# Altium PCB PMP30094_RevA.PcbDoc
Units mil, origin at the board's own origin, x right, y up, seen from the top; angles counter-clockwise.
Board outline 6725 x 2037.5 mil, 2 copper layers (Top Layer, Bottom Layer), stack 62 mil thick; 109 components, 57 nets, 240 pads, 21 vias.
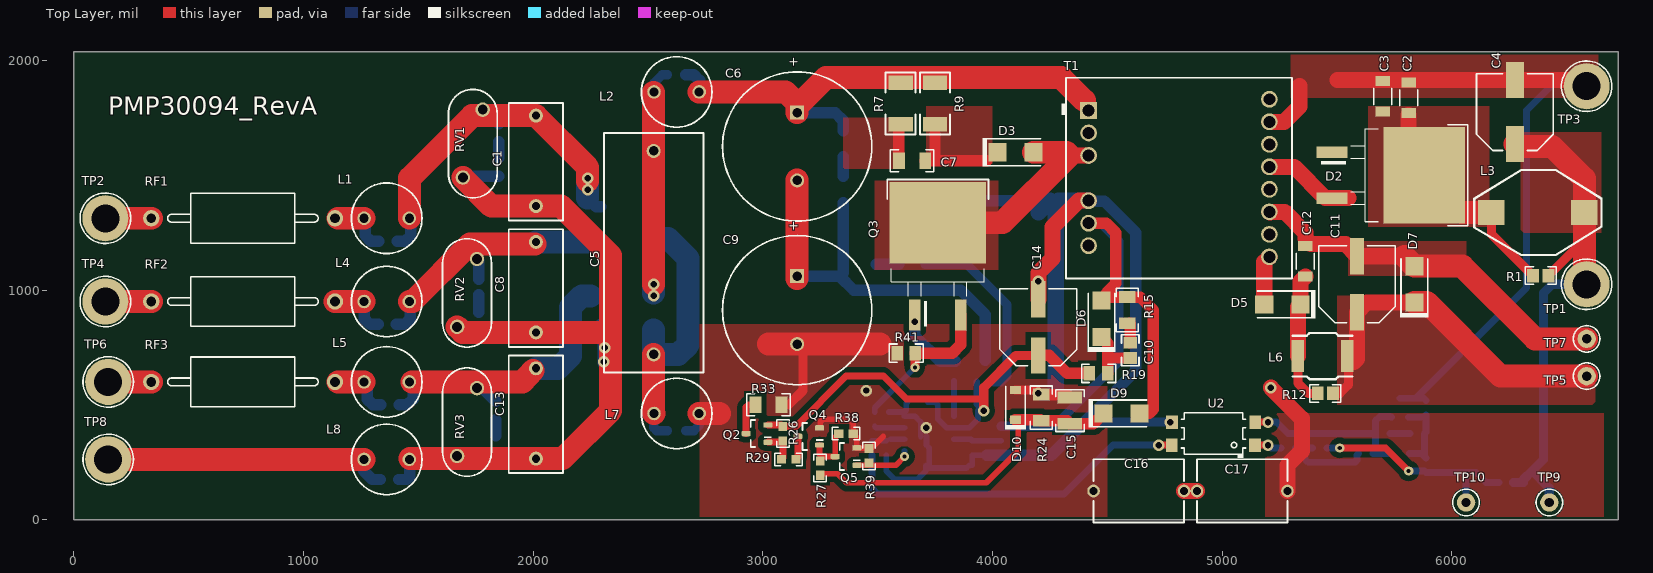
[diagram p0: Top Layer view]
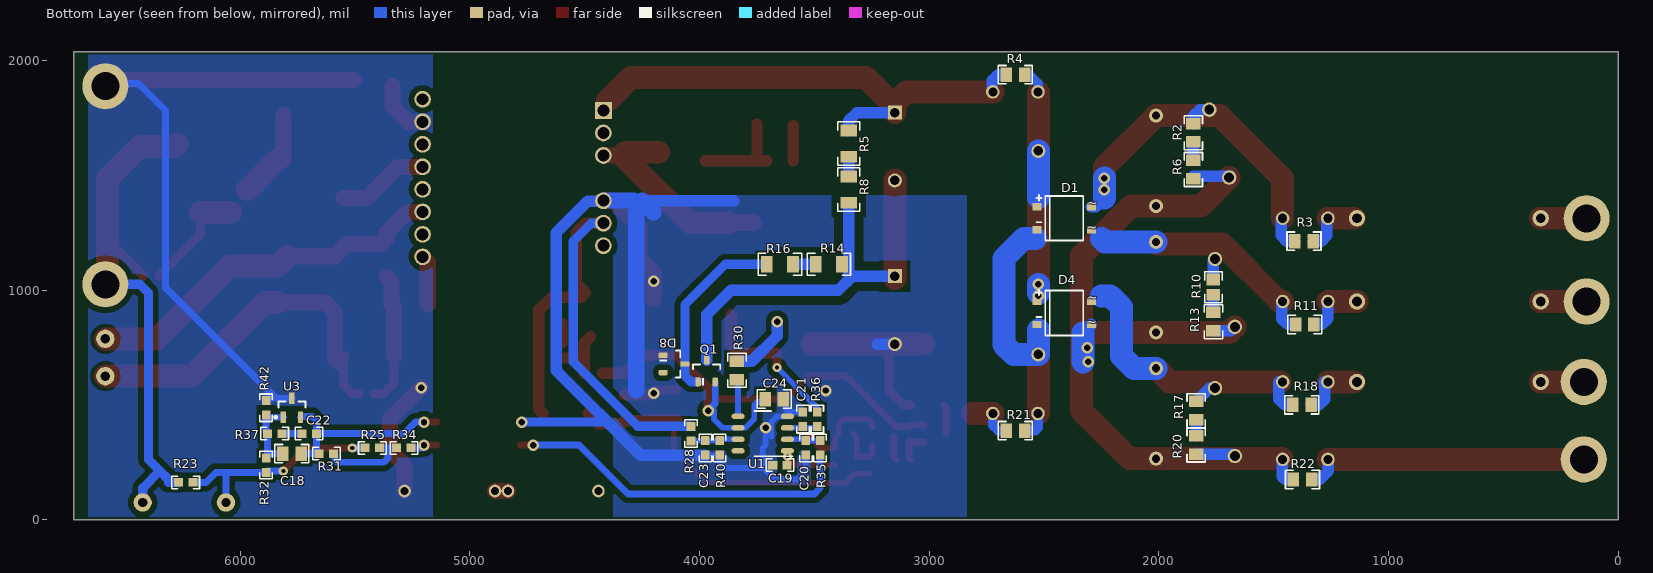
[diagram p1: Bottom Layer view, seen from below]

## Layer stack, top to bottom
Top Solder: solder mask 0.4, Solder Resist, Dk 3.5
Top Layer: signal copper 1.4
Dielectric1: core 59.2, FR-4, Dk 4.8
Bottom Layer: signal copper 1.4
Bottom Solder: solder mask 0.4, Solder Resist, Dk 3.5

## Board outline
0,0 6725,0 6725,2037.5 0,2037.5

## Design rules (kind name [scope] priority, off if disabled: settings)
AcuteAngle [All] p1: minimum=4.50000000000000E+0001 checktracksonly=FALSE
AssemblyTestPointUsage [All] p1: valid=2
Clearance Clearance_2 [InNet('PGND') vs InNet('NetR14_1')] p1: gap=40
Clearance Clearance_1 [InNet('PGND') vs InNet('NetC6_2')] p2: gap=40
Clearance Clearance_Keepouts [((IsTrack Or IsArc) And Not InPoly) And IsFree and IsKeepOut vs ((IsTrack Or IsArc) And Not InPoly) And IsFree and IsKeepOut] p3: gap=0
Clearance Clearance_BoardEdge_MountingHoles [OnCopper and InComponentClass('Mounting Holes') vs IsKeepOut] p4: gap=40
Clearance Clearance_BoardEdge_Poly [OnCopper and InPoly vs IsKeepOut] p5: gap=25
Clearance Clearance_BoardEdge [OnCopper and Not InComponentClass('Logo') and not InComponentClass('FiducialMark') and not InRegion(1000,500,4000,800) and Not IsKeepout vs IsKeepOut] p6: gap=25
Clearance Clearance_Poly [InPolygon] p7: gap=25
Clearance [All] p8: gap=7.87
ComponentClearance ComponentClearance_MountingHoles_FiducialMarks [InComponentClass('Mounting Holes') vs InComponentClass('FiducialMark')] p1: gap=50 collisioncheckmode=3 verticalgap=10 showdistances=FALSE
ComponentClearance ComponentClearance_Shunt [InComponentClass('Header') vs InComponentClass('Shunt')] p2: gap=0 collisioncheckmode=3 verticalgap=0 showdistances=FALSE
ComponentClearance ComponentClearance_Logo [InComponentClass('Logo')] p3: gap=50 collisioncheckmode=3 verticalgap=10 showdistances=FALSE
ComponentClearance ComponentClearance_ScrewToNut [(HasFootprint('NY PMS 440 0025 PH')) vs (HasFootprint('Keystone_1902C'))] p4: gap=5 collisioncheckmode=3 verticalgap=10 showdistances=FALSE
ComponentClearance ComponentClearance_MountingHoles [InComponentClass('Mounting Holes')] p5: gap=20 collisioncheckmode=3 verticalgap=100000 showdistances=FALSE
ComponentClearance ComponentClearance_SmallPassives [HasFootprint('0201*') or HasFootprint('0402*') or HasFootprint('0508') or HasFootprint('0603*') or HasFootprint('0612') or HasFootprint('0805*') or HasFootprint('0815*') or HasFootprint('0830*') or HasFootprint('1206*') or HasFootprint('1210*') or HasFootprint('1808*') or HasFootprint('1812*') or HasFootprint('1825*') or HasFootprint('2010*') or HasFootprint('2220*') or HasFootprint('2225*') or HasFootprint('2512*') or HasFootprint('2728*') or HasFootprint('3518*') vs HasFootprint('0201*') or HasFootprint('0402*') or HasFootprint('0508') or HasFootprint('0603*') or HasFootprint('0612') or HasFootprint('0805*') or HasFootprint('0815*') or HasFootprint('0830*') or HasFootprint('1206*') or HasFootprint('1210*') or HasFootprint('1808*') or HasFootprint('1812*') or HasFootprint('1825*') or HasFootprint('2010*') or HasFootprint('2220*') or HasFootprint('2225*') or HasFootprint('2512*') or HasFootprint('2728*') or HasFootprint('3518*')] p6: gap=20 collisioncheckmode=3 verticalgap=10 showdistances=FALSE
ComponentClearance ComponentClearance_THtoSMT [IsThruComponent vs IsSMTComponent] p7: gap=20 collisioncheckmode=3 verticalgap=30 showdistances=FALSE
ComponentClearance ComponentClearance_THtoTH [IsThruComponent vs IsThruComponent] p8: gap=20 collisioncheckmode=3 verticalgap=20 showdistances=FALSE
ComponentClearance [All] p9: gap=20 collisioncheckmode=3 verticalgap=10 showdistances=FALSE
DiffPairsRouting [All] p1: maxlimit=100 minlimit=10 mostfreqgap=10 toplayer_minwidth=15 toplayer_maxwidth=15 toplayer_prefwidth=15 bottomlayer_minwidth=15 bottomlayer_maxwidth=15 bottomlayer_prefwidth=15 maxuncoupledlength=1000
FabricationTestPointUsage TestPointUsage [All] p1: valid=2 allowmultiple=FALSE
FabricationTestpoint Testpoint [All] p1: side=3 testpointundercomponent=TRUE minsize=40 maxsize=100 preferedsize=60 minholesize=0 maxholesize=40 preferedholesize=32 testpointgrid=1 allowsidetop=TRUE allowsidebottom=TRUE usegrid=TRUE gridtolerance=0.01
FanoutControl Fanout_LCC [IsLCC] p1: bgadir=Out bgaviamode=Centered fanoutstyle=Auto fanoutdirection=Alternating viagrid=1 // Fanout_LCC (Default Rule)
FanoutControl Fanout_BGA [IsBGA] p2: bgadir=Out bgaviamode=Centered fanoutstyle=Auto fanoutdirection=Alternating viagrid=1 // Fanout_BGA (Default Rule)
FanoutControl Fanout_Default [All] p4: bgadir=Out bgaviamode=Centered fanoutstyle=Auto fanoutdirection=Alternating viagrid=1 // Fanout_Default (Default Rule)
FanoutControl Fanout_Small [(CompPinCount < 5)] p5: bgadir=Out bgaviamode=Centered fanoutstyle=Auto fanoutdirection=OutThenIn viagrid=1 // Fanout_Small (Default Rule)
HoleSize [All] p1: absolutevalues=TRUE maxlimit=251 minlimit=8 maxpercent=80.000 minpercent=20.000
MinimumAnnularRing MinimumAnnularRing_ThermalPadVias [IsVia and InAnyComponent] p1: minimumring=5.91
MinimumAnnularRing [All] p2: minimumring=9
MinimumSolderMaskSliver MinimumSolderMaskSliver_Logo [InComponentClass('Logo') vs InComponentClass('Logo')] p1: minsoldermaskwidth=0.7
MinimumSolderMaskSliver [All] p2: minsoldermaskwidth=3.94
PlaneConnect [All] p1: planeconnectstyle=Relief reliefexpansion=10 reliefentries=4 reliefconductorwidth=10 reliefairgap=10
PolygonConnect [All] p1: connectstyle=Direct reliefconductorwidth=10 reliefentries=4 polygonreliefangle="90 Angle" airgapwidth=10
RoutingVias ThermalPadVias [IsVia and InAnyComponent] p1: holewidth=7.87 width=19.68 viastyle="Through Hole" minholewidth=7.87 minwidth=19.68 maxholewidth=12.99 maxwidth=23.62
RoutingVias [All] p2: holewidth=16 width=34 viastyle="Through Hole" minholewidth=7.87 minwidth=26 maxholewidth=40 maxwidth=65
SilkToBoardRegionClearance [Not ((IsComment or IsDesignator) And (Hide <> 'False')) and not InRegion(1000,500,4000,800)] p1:
SilkToSilkClearance SilkToSilkClearance_Pb-FreeLogo [(HasFootprint('Pb-Free_Overlay_Medium') OR HasFootprint('Pb-Free_Overlay_Small')) vs (HasFootprint('Pb-Free_Overlay_Medium') OR HasFootprint('Pb-Free_Overlay_Small'))] p1: silktosilkclearance=0
SilkToSilkClearance [All] p2: silktosilkclearance=0
SilkToSolderMaskClearance SilkToComonentPadClearance [IsPad and InAnycomponent] p1: minsilkscreentomaskgap=0 clearancetoexposedcopper=TRUE
SilkToSolderMaskClearance "Silk to Solder Mask Opening" [All] p2: minsilkscreentomaskgap=0 clearancetoexposedcopper=FALSE
SolderMaskExpansion [All] p1: expansion=1.97
Width [All] p1: maxlimit=100 minlimit=6 preferedwidth=10 checkconnectedcopper=TRUE
15 further rules are at their usual default settings.

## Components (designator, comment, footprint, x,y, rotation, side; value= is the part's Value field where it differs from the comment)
C1 "B32921C3104M" B32921_1300x1200x600 2012.5,1562.5 r270 top
C2 "GRM31CR71A226ME15L" 1206_180 5812.5,1837.5 r270 top
C3 "GRM31CR71A226ME15L" 1206_180 5700,1843.36 r270 top
C4 "EEE-FK1A471P" SM_RADIAL_F 6275,1775 r90 top
C5 "B32653A224J" B32653_2650x2050x1100 2525,1162.5 r270 top
C6 "EKMG401ELL330ML25S" KMG_1600x2500 3150,1625 r270 top
C7 "GRM31BR73A152KW01L" 1206 3650,1562.5 r0 top
C8 "B32921C3104M" B32921_1300x1200x600 2012.5,1012.5 r270 top
C9 "EKMG401ELL330ML25S" KMG_1600x2500 3150,912.5 r270 top
C10 "Used in BOM report" 0805 4600,737.5 r270 top
C11 "EEE-FC1A101P" SM_RADIAL_E 5587.5,1025 r90 top
C12 "C3216X7R1C106K160AC" 1206_190 5362.5,1125 r90 top
C13 "B32921C3104M" B32921_1300x1200x600 2012.5,462.5 r270 top
C14 "EEE-FC1V470P" SM_RADIAL_E 4200,837.5 r90 top
C15 "Used in BOM report" 1210 4337.5,475 r90 top
C16 "DE1E3KX332MN4AP01F" KX_1000x700 4637.5,125 r180 top
C17 "DE1E3KX332MN4AP01F" KX_1000x700 5087.5,125 r180 top
C18 "08055C153KAT2A" 0805_HV 5775,287.5 r180 bottom
C19 "GRM188R71H473KA61D" 0603 3650,237.5 r0 bottom
C20 "GRM1885C1H101JA01D" 0603 3537.5,312.5 r270 bottom
C21 "GRM1885C1H101JA01D" 0603 3550,437.5 r90 bottom
C22 "Used in BOM report" 0603 5700,375 r180 bottom
C23 "Used in BOM report" 0603 3975,312.5 r270 bottom
C24 "08055C105KAT2A" 0805_HV 3675,525 r180 bottom
D1 "MB8S-TP" MBS-1 2412.5,1312.5 r180 bottom
D2 "8TQ080S" DDPAK 5725,1500 r0 top
D3 "US1K-13-F" SMA 4100,1600 r0 top
D4 "MB8S-TP" MBS-1 2412.5,900 r180 bottom
D5 "B1100-13-F" SMA 5262.5,937.5 r180 top
D6 "ES1D-13-F" SMA 4475,875 r90 top
D7 "SMAJ10A" SMA 5837.5,1025 r90 top
D8 "BZX84C16LT1G" SOT-23 4111.42,678.05 r180 bottom
D9 "Used in BOM report" SMA 4562.5,462.5 r0 top
D10 "Used in BOM report" SOD-123 4100,500 r90 top
L1 "744772102" WE_TI_8095_Unshielded 1362.5,1312.5 r0 top
L2 "744772102" WE_TI_8095_Unshielded 2625,1862.5 r0 top
L3 "DO3308P-472MLB" DO3308P 6375,1337.5 r0 top
L4 "744772102" WE_TI_8095_Unshielded 1362.5,950 r0 top
L5 "744772102" WE_TI_8095_Unshielded 1362.5,600 r0 top
L6 "DO1608C-222MLB" DO1608C 5437.5,712.5 r0 top
L7 "744772102" WE_TI_8095_Unshielded 2625,462.5 r0 top
L8 "744772102" WE_TI_8095_Unshielded 1362.5,262.5 r0 top
Q1 "FMMT458TA" SOT-23 3969.19,647.71 r90 bottom
Q2 "MMBT3906-7-F" SOT-23 2975,375 r180 top
Q3 "STB10N95K5" DDPAK 3762.5,1137.5 r90 top
Q4 "MMBT3904-7-F" SOT-23 3200,362.5 r180 top
Q5 "MMBT3904-7-F" SOT-23 3362.5,275 r180 top
R1 "Used in BOM report" 0805 6387.5,1062.5 r0 top
R2 "Used in BOM report" 0805_HV 1850,1685 r90 bottom
R3 "CRCW080510K0FKEA" 0805_HV 1368.31,1212.5 r0 bottom
R4 "CRCW080510K0FKEA" 0805_HV 2625,1937.5 r0 bottom
R5 "CRCW1206549KFKEA" 1206 3350,1637.5 r90 bottom
R6 "Used in BOM report" 0805_HV 1850,1525 r90 bottom
R7 "CRCW201068R0JNEF" 2010 3600,1812.5 r90 top
R8 "CRCW1206549KFKEA" 1206 3350,1437.5 r90 bottom
R9 "CRCW2010100KFKEF" 2010 3750,1812.5 r90 top
R10 "Used in BOM report" 0805 1762.5,1012.5 r90 bottom
R11 "CRCW080510K0FKEA" 0805_HV 1365,850 r0 bottom
R12 "Used in BOM report" 0805 5450,550 r0 top
R13 "Used in BOM report" 0805_HV 1762.5,862.5 r90 bottom
R14 "CRCW1206499KFKEA" 1206 3437.5,1112.5 r180 bottom
R15 "Used in BOM report" 1206 4587.5,912.5 r90 top
R16 "CRCW1206499KFKEA" 1206 3650,1112.5 r180 bottom
R17 "Used in BOM report" 0805_HV 1837.5,475 r90 bottom
R18 "CRCW080510K0FKEA" 0805_HV 1377.5,500 r0 bottom
R19 "CRCW080530R1FKEA" 0805_HV 4462.5,637.5 r0 top
R20 "Used in BOM report" 0805_HV 1837.5,325 r90 bottom
R21 "CRCW080510K0FKEA" 0805_HV 2625,387.5 r0 bottom
R22 "CRCW080510K0FKEA" 0805_HV 1375,175 r0 bottom
R23 "CRCW060349R9FKEA" 0603 6237.5,162.5 r0 bottom
R24 "Used in BOM report" 1206 4212.5,487.5 r270 top
R25 "CRCW06030000Z0EA" 0603 5425,312.5 r0 bottom
R26 "Used in BOM report" 0603 3087.5,375 r90 top
R27 "Used in BOM report" 0603 3250,225 r270 top
R28 "CRCW0603324KFKEA" 0603 4037.5,375 r90 bottom
R29 "Used in BOM report" 0603 3112.5,262.5 r180 top
R30 "CRCW08050000Z0EA" 0805_HV 3837.5,650 r90 bottom
R31 "Used in BOM report" 0603 5625,287.5 r180 bottom
R32 "RCG060310K0FKEA" 0603 5887.5,237.5 r270 bottom
R33 "Used in BOM report" 1206 3025,500 r180 top
R34 "CRCW06032K05FKEA" 0603 5287.5,312.5 r0 bottom
R35 "CRCW06030000Z0EA" 0603 3475,312.5 r270 bottom
R36 "CRCW06031K13FKEA" 0603 3487.5,437.5 r90 bottom
R37 "Used in BOM report" 0603 5850,375 r0 bottom
R38 "Used in BOM report" 0603 3362.5,375 r180 top
R39 "Used in BOM report" 0603 3462.5,278.05 r270 top
R40 "RC0603FR-0724KL" 0603 3912.5,312.5 r90 bottom
R41 "ERJ-6RQF1R2V" 0805_HV 3625,725 r0 top
R42 "CRCW06033K32FKEA" 0603 5887.5,487.5 r270 bottom
RF1 "FW20A10R0JACT-ND" RES_PWR4522 737.5,1312.5 r180 top
RF2 "FW20A10R0JACT-ND" RES_PWR4522 737.5,950 r180 top
RF3 "FW20A10R0JACT-ND" RES_PWR4522 737.5,600 r180 top
RV1 "S10K275E2" VAR_S10K275E2 1737.5,1637.5 r90 top
RV2 "S10K275E2" VAR_S10K275E2 1712.5,987.5 r90 top
RV3 "S10K275E2" VAR_S10K275E2 1712.5,425 r90 top
T1 "750316395" Wurth_750316395 4812.5,1487.5 r0 top
TP1 "Suggest using a net name here" Keystone1503-2 6587.5,1025 r0 top
TP2 "Suggest using a net name here" Keystone1503-2 137.5,1312.5 r0 top
TP3 "Suggest using a net name here" Keystone1503-2 6587.5,1887.5 r0 top
TP4 "Suggest using a net name here" Keystone1503-2 137.5,950 r0 top
TP5 "5000" Keystone5000 6587.5,625 r0 top
TP6 "Suggest using a net name here" Keystone1503-2 150,600 r0 top
TP7 "5001" Keystone5001 6587.5,787.5 r0 top
TP8 "Suggest using a net name here" Keystone1503-2 150,262.5 r0 top
TP9 "5000" Keystone5000 6425,75 r0 top
TP10 "5000" Keystone5000 6062.5,75 r90 top
U1 "UCC28600D" D0008A_N 3725,375 r0 bottom
U2 "FOD817AS" N04C 4962.5,375 r180 top
U3 "LMV431AIMF/NOPB" MF03A_N 5775,487.5 r90 bottom

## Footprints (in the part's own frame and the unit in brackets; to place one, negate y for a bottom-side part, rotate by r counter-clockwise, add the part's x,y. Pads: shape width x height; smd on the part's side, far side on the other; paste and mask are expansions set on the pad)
0603 [mm] "0603 from SM-752 data"
  rect 1x0.95 smd: 1(-0.8,0) 2(0.8,0)
  silkscreen extent -1.52,-0.69 1.52,0.69, body extent -0.87,-0.47 0.87,0.47, height 1
0805 [mm] "0805 from SM-752 data"
  rect 1.3x1.5 smd: 1(-0.85,0) 2(0.85,0)
  silkscreen extent -1.72,-0.97 1.72,0.97, body extent -1.1,-0.72 1.1,0.72, height 1.45
0805_HV [mil] "0805 with 30mil clearance between pads"
  rect 50x63 smd: 1(-40,0) 2(40,0)
  silkscreen extent -74,-40 74,40, body extent -43,-29 43,29, height 57
1206 [mm] "1206 from SM-752 data"
  rect 1.3x1.85 smd: 1(-1.45,0) 2(1.45,0)
  silkscreen extent -2.4,-1.21 2.4,1.21, body extent -1.7,-0.9 1.7,0.9, height 1.35
1206_180 [mm] "1206_180"
  rect 1.1x1.6 smd: 1(-1.7,0) 2(1.7,0)
  silkscreen extent -0.9,-1 0.9,1, body extent -1.75,-0.95 1.75,0.95, height 1.8
1206_190 [mm] "1206_190"
  rect 1.1x1.6 smd: 1(-1.7,0) 2(1.7,0)
  silkscreen extent -0.9,-1 0.9,1, body extent -1.75,-0.95 1.75,0.95, height 1.9
1210 [mm] "1210 from SM-752 data"
  rect 1.3x2.7 smd: 1(-1.45,0) 2(1.45,0)
  silkscreen extent -2.32,-1.57 2.32,1.57, body extent -1.7,-1.35 1.7,1.35, height 1.35
2010 [mm] "Chip Capacitor, Body 5.08x2.54mm, IPC Medium Density"
  rect 1.6x2.7 smd: 1(-2.3,0) 2(2.3,0)
  silkscreen extent -3.42,-1.65 3.42,1.65, body extent -2.73,-1.45 2.73,1.45, height 1.66
B32653_2650x2050x1100 [mm] "TH, 2-Leads, Body 26.5x11mm, Pin Spacing 22.5mm"
  round 1.55 hole 1.05: 1(-11.25,0) 2(11.25,0)
  silkscreen extent -13.25,-5.5 13.25,5.5, body extent -13.25,-5.5 13.25,5.5, height 20.5
B32921_1300x1200x600 [mm] "EPCOS"
  round 1.55 hole 0.9: 1(-5,0) 2(5,0)
  silkscreen extent -6.4,-3 6.6,3, body extent -6.4,-3 6.6,3, height 12
D0008A_N [mm] "SOIC, 8-Leads, Body 4.9x3.9mm, Pitch 1.27mm, IPC Medium Density"
  oval 1.45x0.6 smd: 1(-2.725,1.905) 2(-2.725,0.635) 3(-2.725,-0.635) 4(-2.725,-1.905) 5(2.725,-1.905) 6(2.725,-0.635) 7(2.725,0.635) 8(2.725,1.905)
  silkscreen extent -3.3,-2.5 0.9,2.5, body extent -3,-2.45 3,2.45, height 1.63
DDPAK [mil] "D2-PAK, 3-Pads, Body 9.7x10.4mm (max), TO-263AB, using Vishay Silionix recommended pad sizes"
  rrect8% 135x49.49 smd: 1(-246.06,100) 3(-246.06,-100)
  rrect1% 355x420 smd paste-181.1: 4(155.51,0)
  silkscreen extent -295,-220 344,220, body extent -295,-202 324,202, height 180
DO1608C [mm] "DO1608C"
  rect 1.4x3.56 smd: 1(-2.73,0) 2(2.73,0)
  silkscreen extent -3.3,-2.55 3.3,2.55, body extent -3.27,-2.22 3.33,2.23, height 2.92
DO3308P [mil]
  rect 115x110 smd: 1(-202.5,0) 2(202.5,0)
  silkscreen extent -278,-185 278,185, body extent -255,-185 255,185, height 118
Keystone1503-2 [mm] "Double Turret"
  round 5.1 hole 3.1: 1(0,0)
  silkscreen extent -2.79,-2.79 2.79,2.79, body extent -2.4,-2.4 2.38,2.4, height 9.22
Keystone5000 [mil] "For Keystone 500x miniature loop terminals"
  round 80 hole 40: 1(0,0)
  silkscreen extent -58,-58 58,58, body extent -49,-49 49,49, height 182
Keystone5001 [mil] "For Keystone 500x miniature loop terminals"
  round 80 hole 40: 1(0,0)
  silkscreen extent -58,-58 58,58, body extent -49,-49 49,49, height 182
KMG_1600x2500 [mm] "TH, 2-Leads, 16mm Dia, Pin Spacing 7.5mm"
  rect 1.55x1.55 hole 1.05: 1(-3.75,0)
  round 1.55 hole 1.05: 2(3.75,0)
  silkscreen extent -8.25,-8.25 8.25,8.25, body extent -8.25,-8.25 8.26,8.25, height 26.51
KX_1000x700 [mm] "TH, 2-Leads, Dia 10mm, Lead Spacing 10mm"
  round 1.4 hole 0.9: 1(-5,0) 2(5,0)
  silkscreen extent -5,-3.5 5,3.5, body extent -5.32,-3.5 5.33,3.5, height 12.99
MBS-1 [mm] "SOP, 4-Leads, Body 4.95x4.2mm"
  rect 1x0.8 smd: 1(-3,1.27) 2(3,1.27) 3(3,-1.27) 4(-3,-1.27)
  silkscreen extent -3.08,-2.48 2.1,2.56, body extent -3.45,-2.47 3.45,2.48, height 2.9
MF03A_N [mm] "SOT23, 3-Leads, Body 2.9x1.3mm, Pitch 0.95mm, Lead Span 2.4mm, IPC Medium Density"
  rect 1.3x0.6 smd: 1(-1.05,0.95) 2(-1.05,-0.95) 3(1.05,0)
  silkscreen extent -1.17,-1.5 0.7,1.93, body extent -0.7,-1.5 0.7,1.5, height 1.12
N04C [mm] "FAIRCHILD"
  rect 1.3x1.5 smd mask+0.065: 1(-4.587,1.27) 2(-4.612,-1.27) 3(4.588,-1.27) 4(4.613,1.27)
  silkscreen extent -3.56,-2.3 3.56,2.72, body extent -5.08,-2.3 5.08,2.3, height 3.87
RES_PWR4522 [mm] "Bourns fusible resistor"
  round 1.8 hole 1.1: 1(-10.16,0) 2(10.16,0)
  silkscreen extent -8.3,-2.76 8.35,2.74, body extent -10.58,-2.74 10.58,2.74, height 5.49
SM_RADIAL_E [mm] "8 x 6.2mm:  Panasonic E"
  rect 4x1.6 smd: 1(-3.1,0) 2(3.1,0)
  silkscreen extent -4.25,-4.25 4.25,4.25, body extent -4.25,-4.25 4.25,4.25, height 6.5
SM_RADIAL_F [mm] "8 x 10.2mm:  Panasonic F"
  rect 4x2 smd: 1(-3.55,0) 2(3.55,0)
  silkscreen extent -4.25,-4.25 4.25,4.25, body extent -4.25,-4.25 4.25,4.25, height 10.5
SMA [mm] "Molded Diode, 2-Leads, Body 4.3x2.6mm, IPC Medium Density, based on OnSemi component dimensions and land pattern"
  rect 2x2 smd: 1(-2,0) 2(2,0)
  silkscreen extent -3.66,-1.57 2.79,1.57, body extent -2.6,-1.3 2.6,1.3, height 2.42
SOD-123 [mm] "On Semi recommended land pattern"
  rect 0.915x1.22 smd: 1(-1.637,0) 2(1.637,0)
  silkscreen extent -2.74,-1.17 2.03,1.17, body extent -1.93,-0.9 1.93,0.9, height 1.35
SOT-23 [mm] "SOT23, 3-Leads, Body 2.9x1.3mm, Pitch 0.95mm, Lead Span 2.5mm, IPC Medium Density"
  rrect50% 1x0.6 smd: 1(-1.2,0.95) 2(-1.2,-0.95) 3(1.2,0)
  silkscreen extent -1.62,-1.5 0.7,1.5, body extent -1.16,-1.45 1.21,1.45, height 1
VAR_S10K275E2 [mm] "EPCOS"
  round 1.6 hole 1.1: 1(-3.75,1.1) 2(3.75,-1.1)
  silkscreen extent -6,-2.7 6,2.7, body extent -5.98,-2.7 5.98,2.7, height 14.99
WE_TI_8095_Unshielded [mm] "TH, 2-Leads, Dia 7.8mm, Pin Spacing 5mm"
  round 1.5 hole 1: 1(-2.5,0) 2(2.5,0)
  silkscreen extent -3.9,-3.9 3.9,3.9, body extent -5.52,-5.52 5.52,5.52, height 9.5
Wurth_750316395 [mm] "TH, 14-Leads, Body 25x22.2mm, Pitch 2.49mm"
  rect 1.85x1.85 hole 1.32: 1(-10,7.48)
  round 1.85 hole 1.32: 2(-10,4.99) 3(-10,2.5) 4(-10,-2.5) 5(-10,-4.99) 6(-10,-7.48) 7(10,-8.715) 8(10,-6.225) 9(10,-3.735) 10(10,-1.245) 11(10,1.245) 12(10,3.735) 13(10,6.225) 14(10,8.715)
  silkscreen extent -13,-11.1 12.5,11.1, body extent -12.5,-11.1 12.5,11.1, height 16

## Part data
C1 C8 C13: "CAP, Film, 0.1 µF, 305 V, +/- 20%, TH"
C2 C3: "CAP, CERM, 22 µF, 10 V, +/- 20%, X7R, 1206"
C4: "CAP, AL, 470 µF, 10 V, +/- 20%, 0.16 ohm, SMD"
C5: "CAP, Film, 0.22 µF, 1000 V, +/- 5%, TH"
C6 C9: "CAP, AL, 33 µF, 400 V, +/- 20%, TH"
C7: "CAP, CERM, 1500 pF, 1000 V, +/- 10%, X7R, 1206"
C10 C15 C22 C23: library part Capacitor, "CAP, CERM, xxxF, xxV, [TempCo], xx%, [PackageReference]"
C11: "CAP, AL, 100 µF, 10 V, +/- 20%, 0.4 ohm, SMD"
C12: "CAP, CERM, 10 µF, 16 V, +/- 10%, X7R, 1206_190"
C14: "CAP, AL, 47 µF, 35 V, +/- 20%, 0.4 ohm, SMD"
C16 C17: "CAP, CERM, 3300 pF, 300 V, +/- 20%, E, D10xT7mm"
C18: "CAP, CERM, 0.015 µF, 50 V, +/- 10%, X7R, 0805"
C19: "CAP, CERM, 0.047 µF, 50 V, +/- 10%, X7R, 0603"
C20 C21: "CAP, CERM, 100 pF, 50 V, +/- 5%, C0G/NP0, 0603"
C24: "CAP, CERM, 1 µF, 50 V, +/- 10%, X7R, 0805"
D1 D4: "Diode, Switching-Bridge, 800 V, 0.5 A, 4-Pin TO269AA, Body 4.95 x 4.2 mm, Pitch 2.555 mm"
D2: library part MBRB745PBF, "Diode, Schottky, 80V, 8A, DDPAK"
D3: "Diode, Fast Rectifier, 800 V, 1 A, SMA"
D5: "Diode, Schottky, 100 V, 1 A, SMA"
D6: "Diode, Ultrafast, 200 V, 1 A, SMA"
D7: "Diode, TVS, Uni, 10 V, 400 W, SMA"
D8: "Diode, Zener, 16 V, 225 mW, SOT-23"
D9: library part Diode_Schottky, "Diode, Schottky, xxV, xxA, [PackageReference]"
D10: library part Zener, "Diode, Zener, xxV, xxxmW, [PackageReference]"
L1 L2 L4 L5 L7 L8: library part 744772221, "Inductor, Wirewound, Ferrite, 1000µH, TH"
L3: "Inductor, Drum Core, Ferrite, 4.7 µH, 3.2 A, 0.04 ohm, SMD"
L6: "Inductor, Drum Core, Ferrite, 2.2 µH, 2.3 A, 0.07 ohm, SMD"
Q1: library part "FMMT458TA, Diodes Inc.", "Transistor, NPN, 400 V, 0.225 A, SOT-23"
Q2: library part "MMBT3906-7-F, Diodes Inc.", "Transistor, PNP, 40 V, 0.2 A, SOT-23"
Q3: library part STB8N65M5, "MOSFET, N-CH, 950 V, DDPAK"
Q4 Q5: library part "MMBT3904-7-F, Diodes Inc.", "Transistor, NPN, 40 V, 0.2 A, SOT-23"
R1 R2 R6 R10 R12 R13 R15 R17 R20 R24 R26 R27 R29 R31 R33 R37 R38 R39: library part Resistor, "RES, xxx ohm, x%, xW, [PackageReference]"
R3 R4 R11 R18 R21 R22: "RES, 10.0 k, 1%, 0.125 W, 0805"
R5 R8: "RES, 549 k, 1%, 0.25 W, 1206"
R7: "RES, 68, 5%, 0.75 W, 2010"
R9: "RES, 100 k, 1%, 0.75 W, 2010"
R14 R16: "RES, 499 k, 1%, 0.25 W, 1206"
R19: "RES, 30.1, 1%, 0.125 W, 0805"
R23: "RES, 49.9, 1%, 0.1 W, 0603"
R25 R35: "RES, 0, 5%, 0.1 W, 0603"
R28: "RES, 324 k, 1%, 0.1 W, 0603"
R30: "RES, 0, 5%, 0.125 W, 0805"
R32: "RES, 10.0 k, 1%, 0.1 W, 0603"
R34: "RES, 2.05 k, 1%, 0.1 W, 0603"
R36: "RES, 1.13 k, 1%, 0.1 W, 0603"
R40: "RES, 24.0 k, 1%, 0.1 W, 0603"
R41: "RES, 1.20, 1%, 0.125 W, 0805"
R42: "RES, 3.32 k, 1%, 0.1 W, 0603"
RF1: library part PWR4522AS10R0JA, "RES, 10, 5%, 32W, Fusible, TH"
RF2 RF3: library part PWR4522AS10R0JA, "RES, 10, 5%, 2 W, Fusible, TH"
RV1 RV2 RV3: "Varistor 275V RMS 10MM Radial, TH"
T1: "Transformer, 1100 uH, TH"
TP1 TP2 TP3 TP4 TP6 TP8: library part 1503-2, "Terminal, Turret, TH, Double"
TP5 TP9 TP10: "Test Point, Miniature, Red, TH"
TP7: "Test Point, Miniature, Black, TH"
U1: "Quasi-Resonant Flyback Green-Mode Controller with Current Control, 99 % Duty Cycle, -40 to +105 degC, 8-pin SOIC (D), Green (RoHS & no Sb/Br)"
U2: "Optocoupler, 5 kV, 80-160% CTR, SMT"
U3: "Low-Voltage (1.24V) Adjustable Precision Shunt Regulators, 3-pin SOT-23, Pb-Free"

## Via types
v1: diameter 50, hole 28, Top Layer to Bottom Layer, 17 vias
v2: diameter 40, hole 18, Top Layer to Bottom Layer, 4 vias

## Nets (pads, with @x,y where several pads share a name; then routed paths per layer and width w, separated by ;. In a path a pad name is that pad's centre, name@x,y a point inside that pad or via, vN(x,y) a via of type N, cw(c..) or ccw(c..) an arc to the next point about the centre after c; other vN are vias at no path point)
GND1: C2.1 C3.1 C4.2 C17.1 R42.1 T1.13 TP3.1 U3.3 | length 3761.3
  Top Layer w70: T1.13 5270.08,1732.58 5337.5,1800 5337.5,1887.5 ; v1(5212.5,575) 5347.48,440.02 5347.48,300 5284.35,236.87 C17.1 ; 5502.26,1914.76 C4.2 6560.24,1914.76 TP3.1
  Bottom Layer w30: U3.3 5843.9,528.84 ; R42.1 5877.66,528.84 5843.9,528.84 ; TP3.1 6575,1900 6442.32,1900 6325,1782.68 6325,1009.94 5843.9,528.84
GND2: C11.2 C12.2 D7.2 T1.9 TP7.1 | length 1630.9
  Top Layer w70: T1.9@5209.15,1337.5 T1.9 5272.05,1340.45 5362.5,1250 5362.5,1225 5387.5,1200 5537.5,1200 5587.5,1150 C11.2 5794.19,1147.05
  Top Layer w100: 5794.19,1147.05 D7.2 6046.26,1103.74 6362.5,787.5 TP7.1
NetC1_1: C1.1 D1.2 L1.2 R2.2 R3.2 RV1.2 | length 1634.2
  Top Layer w100: L1.2 1462.5,1314.07 1462.5,1487.5 1734.35,1759.35 C1.1 2237.5,1534.35 v1@2237.5,1475
  Bottom Layer w50: R3.2 1443.31,1212.5 1468.31,1237.5 1468.31,1310.93 L1.2@1466.73,1312.5 ; RV1.2 1821.16,1785.14 1850,1756.3 R2.2 ; 2237.5,1400 2275,1362.5 D1.2
  Bottom Layer w100: 2237.5,1400 v1(2237.5,1487.5)
  other v1: 2237.5,1437.5
NetC1_2: C1.2 C8.2 C13.2 D4.3 L8.2 R6.1 R13.1 R20.1 R22.2 RV1.1 RV2.1 RV3.1 | length 3822.7
  Top Layer w100: L8.2@1464.07,265.65 C13.2 2128.15,265.65 2337.5,475 2337.5,1150 2121.85,1365.65 C1.2 1818.41,1365.65 RV1.1 ; RV2.1 1693.41,815.65 C8.2 2334.35,815.65
  Bottom Layer w50: R22.2 1450,175 1462.5,187.5 L8.2@1462.5,264.07 ; RV2.1 1686.55,822.5 R13.1 ; RV3.1@1676.83,285 R20.1 ; RV1.1@1689.33,1495 R6.1@1850,1495 ; D4.3 2294.39,847.93 2329.82,812.5
  Bottom Layer w100: v1@2329.82,687.5 2329.82,812.5
  other v1: 2308.46,687.5 2312.5,749.11
NetC2_2: C2.2 C3.2 D2.4 L3.1 R1.1 | length 850.9
  Top Layer w40: L3.1 6172.5,1244.04 R1.1
  Top Layer w70: D2.4@5812.5,1568.01 C2.2@5812.5,1762.5
  Top Layer w100: D2.4@5843.01,1562.5 D2.4@5968.01,1437.5 ; D2.4@6043.01,1337.5 L3.1
NetC4_1: C4.1 L3.2 R1.2 R23.2 TP1.1 TP9.1 | length 2326.6
  Top Layer w40: R1.2 6577.5,1219.04
  Top Layer w100: C4.1 6285.24,1625 6437.5,1625 6577.5,1485 L3.2 6577.5,1219.04 6577.5,1035 TP1.1
  Bottom Layer w40: R23.2 6312.5,162.5 6312.5,175 6350,212.5 ; TP9.1 6425,137.5 6350,212.5 ; TP1.1 6437.5,1025 6400,987.5 6400,262.5 6350,212.5
NetC5_1: C5.1 D1.1 D4.1 L2.1 R4.1 | length 1188.8
  Top Layer w100: v1(2525,1025) C5.1 L2.1@2525,1860.93
  Bottom Layer w40: L2.1 2525,1864.07 2525,1900 2562.5,1937.5 R4.1
  Bottom Layer w100: v1@2525,987.99 v1(2525,1025) ; 2525,1403.25 C5.1
  other v1: 2525,975
NetC5_2: C5.2 D1.4 D4.4 L7.1 R21.1 | length 1208
  Top Layer w100: C5.2 2525,464.07 L7.1
  Bottom Layer w40: L7.1 2525,460.93 2525,400 2537.5,387.5 R21.1
  Bottom Layer w100: 2525,825 C5.2 2632.09,719.59 2675,762.5 2675,1137.5 2587.5,1225 2537.5,1225
NetC6_1: C6.1 L2.2 R4.2 R5.2 R7.2 R9.2 T1.1 | length 2196.3
  Top Layer w100: L2.2 3100,1862.5 3150,1812.5 ; C6.1 3150,1800 3275,1925 4300,1925 4400,1825
  Bottom Layer w50: R4.2 2700,1937.5 2725,1912.5 2725,1864.07 L2.2 ; C6.1 3314.86,1772.64 3350,1737.5 R5.2
NetC6_2: C6.2 C9.1 Q1.3 R8.1 R14.2 | length 1842.8
  Top Layer w100: C9.1@3150,1050 C9.1 C6.2 C6.2@3150,1479.72
  Bottom Layer w50: C9.1 3335.14,1060.14 ; R8.1 3350,1075 3335.14,1060.14 ; Q1.3 3969.19,893.31 3862.5,1000 3395.28,1000 3335.14,1060.14
NetC7_1: C7.1 R7.1 | length 152.4
  Top Layer w50: C7.1 R7.1@3592.91,1714.86
NetC7_2: C7.2 D3.1 R9.1 | length 402.4
  Top Layer w50: C7.2 3975,1562.5 ; 3750,1587.5 R9.1
NetC8_1: C8.1 D1.3 L4.2 R10.2 R11.2 RV2.2 | length 1158.9
  Top Layer w50: RV2.2@1755.81,1156.69 1755.81,1181.69
  Top Layer w100: L4.2 1475,950 1725,1200 C8.1@2009.35,1200
  Bottom Layer w50: R11.2 1440,850 1465,875 1465,948.43 L4.2@1463.43,950 ; RV2.2 1762.5,1128.44 R10.2
  Bottom Layer w100: C8.1 2234.35,1209.35 2250,1225
NetC10_1: C10.1 R15.1 | length 84.4
  Top Layer w50: C10.1 R15.1@4600,855.41
NetC10_2: C10.2 D6.1 R19.2 | length 268
  Top Layer w50: D6.1 4502.5,768.76 4502.5,703.13 ; R19.2 4502.5,703.13 ; C10.2 4503.41,704.04 4502.5,703.13
NetC11_1: C11.1 D7.1 L6.2 R12.2 TP5.1 | length 1580.8
  Top Layer w40: R12.2 5512.5,550 5550,587.5 5550,707.48 L6.2
  Top Layer w70: 5575,687.5 5587.5,700 C11.1 5630.81,946.26 D7.1
  Top Layer w100: D7.1 5891.24,946.26 6212.5,625 TP5.1
NetC12_1: C12.1 D5.1 L6.1 R12.1 | length 581.7
  Top Layer w40: L6.1 5330.02,594.98 5375,550 R12.1
  Top Layer w70: L6.1 5330.02,926.28 D5.1 5341.24,1036.81 C12.1
NetC13_1: C13.1 D4.2 L5.2 R17.2 R18.2 RV3.2 | length 1292.5
  Top Layer w100: L5.2@1473.43,600 1953.15,600 C13.1@2000,650
  Bottom Layer w50: R18.2 1452.5,500 1477.5,525 1477.5,598.43 L5.2@1475.93,600 ; RV3.2 1779.86,572.64 R17.2
  Bottom Layer w100: C13.1 2109.35,659.35 2162.5,712.5 2162.5,925 2212.5,975 2250,975
NetC15_1: C15.1 D9.1 D10.1 R24.2 R27.2 | length 1474.5
  Top Layer w25: R27.2@3262.5,199.75 3262.75,200 3325,200 3364.47,160.53 3973.03,160.53 4112.5,300 4112.5,423.03 D10.1
  Top Layer w50: D10.1 4207.38,435.53 R24.2 4325,430.41 C15.1 4439.17,417.91 D9.1
NetC16_1: C16.1 C17.2 | length 56.3
  Top Layer w70: C16.1 C17.2
NetC18_1: C18.1 R32.1 R37.2 R42.2 U3.1 | length 342.8
  Bottom Layer w30: U3.1 5877.66,446.16 R42.2 5887.5,381 R37.2 R32.1@5881.5,275 ; C18.1 5869,287.5 R32.1@5881.5,275 ; R32.1 R32.1@5881.5,275
NetC18_2: C18.2 C22.2 R31.1 U2.2 U3.2 | length 821.2
  Top Layer w30: U2.2 v1(5200,425)
  Bottom Layer w30: v1(5200,425) 5237.5,425 5287.5,375 C22.2 ; R31.1 C18.2@5722.5,287.5 ; R31.1@5668.5,299.51 C22.2 ; U3.2 5733.76,450 5687.5,450 5668.5,431 C22.2
NetC19_1: C19.1 Q5.1 R39.2 U1.1 | length 248.5
  Top Layer w25: Q5.1 3409.84,237.5 3580.22,237.5 v2(3617.72,275)
  Bottom Layer w25: v2(3617.72,275) U1.1
NetC20_1: C20.1 R35.1 U1.2 | length 124.2
  Bottom Layer w25: R35.1 C20.1 ; C20.1@3556,350 U1.2
NetC21_1: C21.1 R36.1 U1.3 | length 132.7
  Bottom Layer w25: R36.1 3493.5,400 U1.3
NetC22_1: C22.1 R37.1 | length 87
  Bottom Layer w30: C22.1 R37.1
NetC23_1: C23.1 R28.1 R40.2 U1.7 | length 207.9
  Bottom Layer w25: U1.7 3906.5,350 R40.2 4037.01,344 R28.1
NetD2_3: D2.3 T1.11 | length 400.3
  Top Layer w70: T1.11 5313.48,1536.52 5450,1400 D2.3 5550,1400
NetD3_2: D3.2 Q3.4 T1.3 | length 940.6
  Top Layer w70: Q3.4 Q3.4@3875,1293.01 ; 4335.93,1585.93 T1.3
  Top Layer w100: Q3.4@3875,1293.01 4043.01,1293.01 4335.93,1585.93 4321.85,1600 D3.2
NetD5_2: D5.2 T1.7 | length 216.2
  Top Layer w70: D5.2 5183.76,1121.95 T1.7
NetD6_2: D6.2 D9.2 R15.2 R28.2 T1.5 | length 2423.7
  Top Layer w50: T1.5 4496.46,1291.04 4537.5,1250 4537.5,1028.74 4496.88,988.12 4515.41,969.59 R15.2 4642.91,969.59 4700,912.5 4700,479.92 4682.58,462.5
  Bottom Layer w40: R28.2 4269,406.5 4550,687.5 4550,1212.5 4471.46,1291.04 T1.5
NetD8_3: D8.3 Q1.1 R16.1 | length 807.9
  Bottom Layer w40: R16.1 3887.5,1112.5 4064.18,935.82 D8.3 4064.18,626.68 4037.96,600.46 Q1.1
NetL1_1: L1.1 R3.1 RF1.1 | length 260.1
  Top Layer w100: RF1.1@1150,1312.5 L1.1
  Bottom Layer w50: L1.1@1269.88,1312.5 1268.31,1310.93 1268.31,1237.5 1293.31,1212.5 R3.1
NetL4_1: L4.1 R11.1 RF2.1 | length 272.6
  Top Layer w100: RF2.1 L4.1
  Bottom Layer w50: L4.1@1266.57,950 1265,948.43 1265,875 1290,850 R11.1
NetL5_1: L5.1 R18.1 RF3.1 | length 260.1
  Top Layer w100: RF3.1@1150,600 L5.1
  Bottom Layer w50: L5.1@1279.07,600 1277.5,598.43 1277.5,525 1302.5,500 R18.1
NetL8_1: L8.1 R22.1 TP8.1 | length 1250.5
  Top Layer w100: TP8.1 L8.1
  Bottom Layer w50: L8.1@1262.5,260.93 1262.5,212.5 1300,175 R22.1
NetQ2_1: Q2.1 R26.1 R29.2 | length 151.4
  Top Layer w30: Q2.1 3081.59,337.6 R26.1 3087.5,269 R29.2
NetQ2_3: Q2.3 R33.2 | length 129
  Top Layer w30: Q2.3 2927.76,490.26 2937.5,500
NetQ3_1: Q3.1 R30.2 | length 283.1
  Bottom Layer w50: v1(3662.5,862.5) 3662.5,800 3772.5,690 R30.2
NetQ3_3: Q3.3 R36.2 R41.2 | length 669.4
  Top Layer w40: v2(3662.5,662.5) R41.2@3662.5,722.5
  Top Layer w50: R41.2@3666,724 R41.2 3825,725 3862.5,762.5 Q3.3
  Bottom Layer w25: R36.2 3487.5,487.5 v2(3662.5,662.5)
NetQ4_1: Q4.1 Q5.3 R27.1 R38.2 | length 218.8
  Top Layer w25: Q4.1 3247.24,284.98 3257.23,275 Q5.3 3315.26,359.25 R38.2
NetQ4_3: Q4.3 R29.1 | length 103.6
  Top Layer w30: R29.1 3152.76,271.26 Q4.3
NetR2_1: R2.1 R6.2 | length 70
  Bottom Layer w50: R6.2@1850,1575 R2.1
NetR5_1: R5.1 R8.2 | length 85.8
  Bottom Layer w50: R8.2 R5.1
NetR10_1: R10.1 R13.2 | length 76.5
  Bottom Layer w50: R13.2 R10.1
NetR14_1: R14.1 R16.2 | length 98.3
  Bottom Layer w50: R14.1 R16.2
NetR17_1: R17.1 R20.2 | length 70
  Bottom Layer w50: R20.2 R17.1
NetR23_1: R23.1 R25.2 R32.2 TP10.1 | length 942.6
  Top Layer w30: v2(5512.5,312.5) 5712.5,312.5 v2(5812.5,212.5)
  Bottom Layer w30: R25.2 v2(5512.5,312.5) ; v2(5812.5,212.5) 5881,212.5 R32.2 6062.5,206 ; TP10.1 6062.5,206 ; R23.1 6150,162.5 6106.5,206 6062.5,206
NetR25_1: R25.1 R31.2 R34.2 | length 392
  Bottom Layer w30: R34.2 5356.25,312.5 ; R25.1 5356.25,312.5 ; R31.2 5587.5,281.5 5587.5,258.96 5578.54,250 5375,250 5356.25,268.75 5356.25,312.5
NetR30_1: R30.1 U1.5 | length 154.8
  Bottom Layer w25: U1.5 R30.1@3832.28,604.78
NetR34_1: R34.1 U2.1 | length 118.1
  Top Layer w30: U2.1 v1(5200,325)
  Bottom Layer w30: v1(5200,325) 5212.5,312.5 R34.1
NetR35_2: R35.2 U2.4 | length 1547.8
  Top Layer w30: v1(4725,325) U2.4
  Bottom Layer w30: R35.2 3475,137.5 3500,112.5 4312.5,112.5 4525,325 v1(4725,325)
NetRF1_2: RF1.2 TP2.1 | length 200
  Top Layer w100: TP2.1 RF1.2
NetRF2_2: RF2.2 TP4.1 | length 187.5
  Top Layer w100: TP4.1@150,950 RF2.2
NetRF3_2: RF3.2 TP6.1 | length 187.5
  Top Layer w100: TP6.1 RF3.2
PGND: C9.2 C14.2 C15.2 C16.2 C19.2 C20.2 C21.2 C23.2 C24.2 D8.1 D10.2 L7.2 Q4.2 Q5.2 R21.2 R24.1 R33.1 R38.1 R39.1 R40.1 R41.1 T1.4 U1.4 U2.3 | length 6677.4
  Top Layer w25: Q4.2 3250,402.66 3250,425 3262.5,437.5 3375.49,437.5 3394,419 R38.1 ; R38.1@3409.74,359.25 Q5.2 R39.1@3459.65,312.4 ; R39.1 3472.05,309.55 3525,362.5
  Top Layer w40: R33.1 3112.5,500 3175,562.5 3175,739.86 ; D10.2 R24.1@4192.62,564.47
  Top Layer w50: R24.1 C15.2@4325,544.59
  Top Layer w70: C14.2 4200,1075 4262.5,1137.5 4262.5,1275 4376.57,1389.07 T1.4
  Top Layer w100: L7.2 2812.5,462.5 ; 3025.79,764.86 C9.2 3511.14,764.86
  Bottom Layer w25: C20.2 3537.5,212.5 3575,175 3672.48,175 3709.98,212.5 3709.98,234.98 3712.5,237.5 ; C21.2 3616.44,469 3617.72,467.72 ; C24.2@3631,512.5 3625,506.5 3625,475 3617.72,467.72 ; 3687.5,362.5 3687.5,425 3662.5,450 U1.4 3617.72,467.72 ; 3712.5,362.5 3712.5,325 3725,312.5 3725,225 3887.5,225 3900,237.5 3912.5,237.5 R40.1 C23.2
  Bottom Layer w40: R21.2 2700,387.5 2725,412.5 2725,425 2723.43,426.57 L7.2 ; 4425,425 v1(4775,425)
  Bottom Layer w50: C9.2 3227.36,764.86 ; 3851.57,1389.07 4251.57,1389.07 4287.5,1389.07 ; C23.2 4256,281 4625,650 4625,1250 4487.5,1387.5 4420.37,1387.5 T1.4
  Bottom Layer w70: 4200,1337.5 4251.57,1389.07 ; 4275.78,562.5 4275.78,1337.5 ; 4287.5,1389.07 T1.4
  other v1: 3712.5,400 4200,550 3450,562.5 4200,1037.5
VDD: C14.1 C24.1 Q1.2 Q2.2 R19.1 R26.2 U1.6 | length 2209.7
  Top Layer w30: Q2.2 R26.2@3081.59,412.4 ; R26.2 3144,406.5 3362.5,625 3525,625 3625,525 3962.5,525
  Top Layer w40: v1(3962.5,475) 3962.5,525 3962.5,575 4102.95,715.45 C14.1
  Top Layer w50: C14.1 4247.05,715.45 4325,637.5 R19.1
  Bottom Layer w25: C24.1@3719,512.5 3750,512.5 3762.5,500 3762.5,437.5 3800,400 U1.6 3900,400 3937.5,437.5 v1@3937.5,475
  Bottom Layer w30: Q1.2 3931.79,505.71 v1(3962.5,475)
pads on no net: D2.1 D8.2 T1.2 T1.6 T1.8 T1.10 T1.12 T1.14 U1.8

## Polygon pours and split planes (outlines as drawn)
GND1 on Bottom Layer "Bottom Layer-No Net 1" (solid, pour order 14): 5162.5,2025 6662.5,2025 6662.5,12.5 5162.5,12.5
PGND on Bottom Layer "Bottom Layer-No Net" (solid, pour order 0): 2837.5,1412.5 4375,1412.5 4375,12.5 2837.5,12.5
NetC4_1 on Top Layer "Top Layer-No Net 6" (solid, pour order 16): 6650,1250 6312.5,1250 6300,1262.5 6300,1687.5 6650,1687.5
GND1 on Top Layer "Top Layer-No Net 5" (solid, pour order 12): 6637.5,1837.5 5300,1837.5 5300,2025 6637.5,2025
NetC2_2 on Top Layer "Top Layer-No Net 4" (solid, pour order 10): 5637.5,1800 6075,1800 6162.5,1800 6162.5,1275 5637.5,1275
NetD3_2 on Top Layer "Top Layer-No Net 3" (solid, pour order 8): 3487.5,1475 4025,1475 4025,1087.5 3487.5,1087.5
NetC7_1 on Top Layer "Top Layer-No Net 2" (solid, pour order 6): 3350,1750 3612.5,1750 3612.5,1527.07 3354.92,1527.07 3350,1531.99
NetC7_2 on Top Layer "Top Layer-No Net 1" (solid, pour order 4): 3712.5,1800 3712.5,1550 4000,1550 4000,1800
PGND on Top Layer "Top Layer-No Net" (solid, pour order 2): 2725,850 4500,850 4500,12.5 2725,12.5
NetC11_1 on Top Layer "Top Layer-No Net 7" (solid, pour order 18): 5502.5,975 5906.4,975 5912.5,975 6225,662.5 6625,662.5 6625,512.5 6612.5,500 5502.5,500
GND2 on Top Layer "Top Layer-No Net 8" (solid, pour order 20): 5550,1212.5 6062.5,1212.5 6062.5,1062.5 5550,1062.5
GND1 on Top Layer "Top Layer-No Net 9" (solid, pour order 22): 5187.5,462.5 6662.5,462.5 6662.5,12.5 5187.5,12.5

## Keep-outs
Keep-Out Layer:
  text ".Layer_Name" at 577,-858.49 h60

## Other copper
Top Layer:
  text ".Layer_Name" at 577,-858.49 h60
Bottom Layer:
  text ".Layer_Name" at 577,-858.49 h60

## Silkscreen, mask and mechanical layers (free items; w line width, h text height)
Top Overlay:
  text "PMP30094_RevA" at 150,1762.5 h80
  text ".Layer_Name" at 577,-858.49 h40
Bottom Overlay:
  text ".Layer_Name" at 577,-858.49 h40
Top Paste:
  text ".Layer_Name" at 577,-858.49 h60
Bottom Paste:
  text ".Layer_Name" at 577,-858.49 h60
Top Solder:
  text ".Layer_Name" at 577,-858.49 h60
  text ".Layer_Name" at 577,-858.49 h60
Bottom Solder:
  text ".Layer_Name" at 577,-858.49 h60
Drill Guide:
  text ".Layer_Name" at 577,-858.49 h60
M1 Board Outline:
  the board outline again, w10
  text ".Layer_Name" at 577,-858.49 h60
M2 Board Dimensions:
  rectangle: 0,-275 125,-150
  rectangle: 125,-400 500,-275
  lines w7: 0,-275 1000,-275 ; 125,-400 125,-150 ; 250,-400 250,-150 ; 500,-400 500,-150 ; 750,-400 750,-150 ; 0,-400 1000,-400 1000,-150 0,-150 0,-400
  text ".Layer_Name" at 577,-858.49 h60
M3 3D STEP Top:
  text ".Layer_Name" at 577,-858.49 h60
M4 3D STEP Bottom:
  text ".Layer_Name" at 577,-858.49 h60
M5 Assembly Top:
  lines w10: -292,-930.17 6308,-930.17 ; -292,-726.83 6310,-726.83 ; -292,-523.5 -292,-1133.5 3713,-1133.5 6310,-1133.5 6310,-523.5 -291.5,-523.5 -291.5,-1133.5 1284,-1133.5 ; 2173,-1133.5 2173,-523.5 ; 3440,-726.83 3440,-523.5 ; 4280,-726.83 4280,-523.5 ; 4902,-1140 4902,-937.17
  text "PCB VIEWED FROM TOP SIDE" at -228.5,-655.67 h60
  text "BOARD #:" at 2248,-655.67 h60
  text ".PRJ_Number" at 2793.5,-655.67 h60
  text "REV:" at 3638,-655.67 h60
  text ".PCB_Rev" at 3929.5,-655.67 h60
  text "SVN REV:" at 4476,-655.67 h60
  text ".VersionControl_RevNumber" at 4982,-655.67 h60
  text "TID #:" at 2248,-859 h60
  text ".TID" at 2793.5,-859 h60
  text "PLOT NAME =" at -228.5,-1064.34 h60
  text ".plot_File_Name" at 577,-1064.34 h60
  text "GENERATED    :" at 2250,-1064.34 h60
  text ".Print_Date" at 3119.5,-1064.34 h60
  text ".Print_Time" at 3848.5,-1064.34 h60
  text "TEXAS INSTRUMENTS" at 5113,-1064.34 h60
M6 Assembly Bottom:
  lines w10: -292.5,-727.33 6309.5,-727.33 ; -290.5,-930.67 6309.5,-930.67 ; 1115.5,-1140.5 1115.5,-937.67 ; 1737.5,-727.33 1737.5,-524 ; 2577.5,-727.33 2577.5,-524 ; 3844.5,-1134 3844.5,-524 ; 4733.5,-1134 6309,-1134 6309,-524 -292.5,-524 -292.5,-1134 2304.5,-1134 6309.5,-1134 6309.5,-524
  text ".VersionControl_RevNumber" at 1035.5,-656.17 h60
  text "SVN REV:" at 1541.5,-656.17 h60
  text ".PCB_Rev" at 2088,-656.17 h60
  text "REV:" at 2379.5,-656.17 h60
  text ".PRJ_Number" at 3224,-656.17 h60
  text "BOARD #:" at 3769.5,-656.17 h60
  text "PCB VIEWED FROM BOTTOM SIDE" at 6246,-656.17 h60
  text ".TID" at 3224,-859.5 h60
  text "TID #:" at 3769.5,-859.5 h60
  text "TEXAS INSTRUMENTS" at 904.5,-1064.84 h60
  text ".Print_Time" at 2169,-1064.84 h60
  text ".Print_Date" at 2898,-1064.84 h60
  text "GENERATED    :" at 3767.5,-1064.84 h60
  text ".plot_File_Name" at 5440.5,-1064.84 h60
  text "PLOT NAME =" at 6246,-1064.84 h60
M9 Title Sheet:
  drawing of 57 lines, arcs and shapes, not listed
  text "1" at 739.84,8036.5 h70
  text "2" at 3235.5,8036.5 h70
  text "3" at 5724.84,8036.5 h70
  text "4" at 8231.51,8036.5 h70
  text "5" at 10730.5,8036.5 h70
  text "6" at 13235.5,8036.5 h70
  text "A" at -416.5,6893.5 h70
  text "A" at 14383.5,6893.5 h70
  text "B" at -416.5,4513.5 h70
  text "B" at 14383.5,4513.5 h70
  text "C" at -416.5,2138.5 h70
  text "C" at 14383.5,2138.5 h70
  text "PROJECT TITLE:" at 11343.5,277.5 h45
  text ".PRJ_Title" at 11393.5,144.17 h70
  text "DESIGNED FOR:" at 11343.5,-23.5 h45
  text ".PRJ_Customer" at 11393.5,-163.5 h70
  text "D" at -416.5,-231.5 h70
  text "D" at 14383.5,-231.5 h70
  text "FILE NAME:" at 11343.5,-323.5 h45
  text ".PCB_File_Name_No_Path" at 11393.5,-443.5 h70
  text "Texas Instruments (TI) and/or its licensors do not warrant the accuracy or completeness of this specification" at 6374,-605.34 h45
  text "ENGINEER:" at 11343.5,-613.5 h45
  text "LAYOUT BY:" at 12848.5,-613.5 h45
  text "or any information contained therein. TI and/or its licensors do not warrant that this design will meet" at 6329.01,-718 h45
  text ".PRJ_Engineer" at 11393.5,-768.49 h70
  text ".PCB_Layout" at 12899,-768.49 h70
  text "the specifications, will be suitable for your application or fit for any particular purpose, or will operate in" at 6329.01,-830.67 h45
  text ".Layer_Name" at 577,-858.49 h60
  text "ALTIUM DESIGNER VERSION:" at 12848.5,-923.5 h45
  text "an implementation. TI and/or its licensors do not warrant that the design is production worthy. You should" at 6329.01,-943.33 h45
  text "completely validate and test your design implementation to confirm the system functionality for your application." at 6374,-1056 h45
  text ".print_Scale" at 11393.5,-1056.83 h70
  text ".Application_BuildNumber" at 12899,-1056.83 h70
  text "1" at 739.84,-1263.5 h70
  text "2" at 3235.5,-1263.5 h70
  text "3" at 5724.84,-1263.5 h70
  text "4" at 8231.51,-1263.5 h70
  text "5" at 10730.5,-1263.5 h70
  text "6" at 13235.5,-1263.5 h70
M10 Fab Notes:
  text ".Layer_Name" at 577,-858.49 h60
M11 Gerber Information:
  lines w10: -292,-930.17 6308,-930.17 ; -292,-726.83 6310,-726.83 ; -292,-523.5 -292,-1133.5 3713,-1133.5 6310,-1133.5 6310,-523.5 -291.5,-523.5 -291.5,-1133.5 1284,-1133.5 ; 2173,-1133.5 2173,-523.5 ; 3440,-726.83 3440,-523.5 ; 4280,-726.83 4280,-523.5 ; 4902,-1140 4902,-937.17
  text "ALL ARTWORK VIEWED FROM TOP SIDE" at -228.5,-655.67 h60
  text "BOARD #:" at 2248,-655.67 h60
  text ".PRJ_Number" at 2793.5,-655.67 h60
  text "REV:" at 3638,-655.67 h60
  text ".PCB_Rev" at 3929.5,-655.67 h60
  text "SVN REV:" at 4476,-655.67 h60
  text ".VersionControl_RevNumber" at 4982,-655.67 h60
  text "LAYER NAME =" at -228.5,-858.49 h60
  text "TID #:" at 2248,-859 h60
  text ".TID" at 2793.5,-859 h60
  text "PLOT NAME =" at -228.5,-1064.34 h60
  text ".plot_File_Name" at 577,-1064.34 h60
  text "GENERATED    :" at 2250,-1064.34 h60
  text ".Print_Date" at 3119.5,-1064.34 h60
  text ".Print_Time" at 3848.5,-1064.34 h60
  text "TEXAS INSTRUMENTS" at 5113,-1064.34 h60
M12 Stackup:
  text ".Layer_Name" at 577,-858.49 h60
M13 Component Bodies Top:
  text ".Layer_Name" at 577,-858.49 h60
M14 Component Bodies Bottom:
  text ".Layer_Name" at 577,-858.49 h60
M15 Courtyards Top:
  text ".Layer_Name" at 577,-858.49 h60
M16 Courtyards Bottom:
  text ".Layer_Name" at 577,-858.49 h60
Drill Drawing:
  text ".Layer_Name" at 577,-858.49 h60

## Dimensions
0,-400 to 1000,-400 on M2 Board Dimensions
0,0 to 0,2037.5 on M2 Board Dimensions
0,0 to 6725,0 on M2 Board Dimensions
